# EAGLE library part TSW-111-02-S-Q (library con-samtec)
THROUGH-HOLE .025" SQ POST HEADER Source: Samtec TSW.pdf
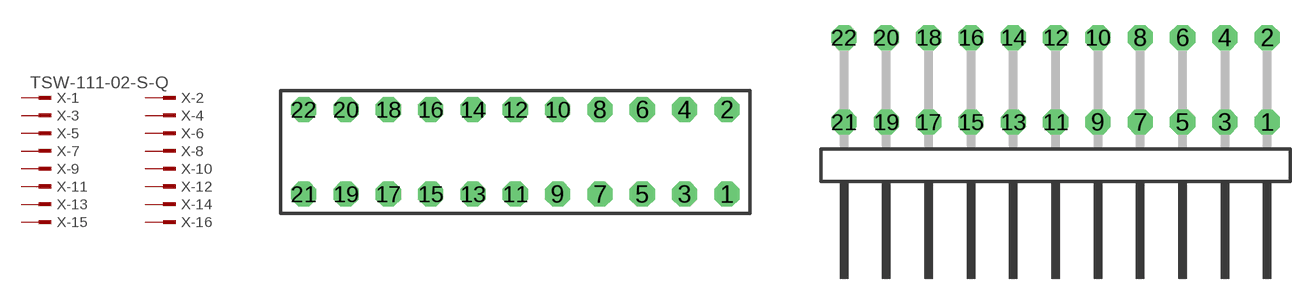
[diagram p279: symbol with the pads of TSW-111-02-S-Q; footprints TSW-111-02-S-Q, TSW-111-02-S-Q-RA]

Designator prefix X; gates -1=MPINV -2=MPIN -3=MPIN -4=MPIN -5=MPIN -6=MPIN -7=MPIN -8=MPIN -9=MPIN -10=MPIN -11=MPIN -12=MPIN -13=MPIN -14=MPIN -15=MPIN -16=MPIN -17=MPIN -18=MPIN -19=MPIN -20=MPIN -21=MPIN -22=MPIN

## TSW-111-02-S-Q (OC_FARNELL: unknown; OC_NEWARK: unknown)  [TSW-111-02-S-Q]
1  -1:1  pas
2  -2:1  pas
3  -3:1  pas
4  -4:1  pas
5  -5:1  pas
6  -6:1  pas
7  -7:1  pas
8  -8:1  pas
9  -9:1  pas
10  -10:1  pas
11  -11:1  pas
12  -12:1  pas
13  -13:1  pas
14  -14:1  pas
15  -15:1  pas
16  -16:1  pas
17  -17:1  pas
18  -18:1  pas
19  -19:1  pas
20  -20:1  pas
21  -21:1  pas
22  -22:1  pas

## TSW-111-02-S-Q-RA (OC_FARNELL: unknown; OC_NEWARK: unknown)  [TSW-111-02-S-Q-RA]
Pads as for TSW-111-02-S-Q

## Footprint TSW-111-02-S-Q (pad centres in mm)
THROUGH-HOLE .025" SQ POST HEADER Source: Samtec TSW.pdf
drill 1 pad 1.5 octagon: 1 12.7,-2.54; 2 12.7,2.54; 3 10.16,-2.54; 4 10.16,2.54; 5 7.62,-2.54; 6 7.62,2.54; 7 5.08,-2.54; 8 5.08,2.54; 9 2.54,-2.54; 10 2.54,2.54; 11 0,-2.54; 12 0,2.54; 13 -2.54,-2.54; 14 -2.54,2.54; 15 -5.08,-2.54; 16 -5.08,2.54; 17 -7.62,-2.54; 18 -7.62,2.54; 19 -10.16,-2.54; 20 -10.16,2.54; 21 -12.7,-2.54; 22 -12.7,2.54

## Footprint TSW-111-02-S-Q-RA (pad centres in mm)
THROUGH-HOLE .025" SQ POST HEADER Source: Samtec TSW.pdf
drill 1 pad 1.5 octagon: 1 12.7,1.524; 2 12.7,6.604; 3 10.16,1.524; 4 10.16,6.604; 5 7.62,1.524; 6 7.62,6.604; 7 5.08,1.524; 8 5.08,6.604; 9 2.54,1.524; 10 2.54,6.604; 11 0,1.524; 12 0,6.604; 13 -2.54,1.524; 14 -2.54,6.604; 15 -5.08,1.524; 16 -5.08,6.604; 17 -7.62,1.524; 18 -7.62,6.604; 19 -10.16,1.524; 20 -10.16,6.604; 21 -12.7,1.524; 22 -12.7,6.604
